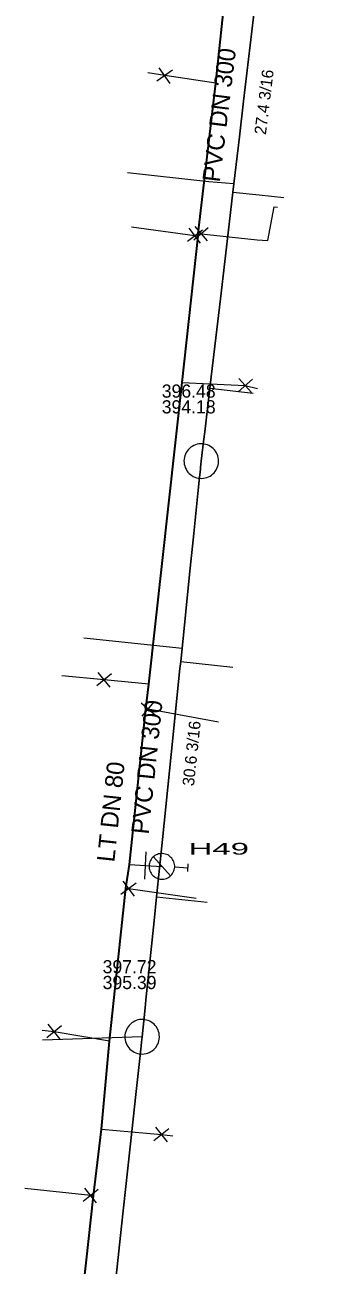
# Model space of a CAD drawing. Extents: x -772952 to -772403, y -1033777 to -1033210.
# Drawn here: x -772699.6 to -772678.8, y -1033502.9 to -1033418.1 of the extents above; entities that cross this region are included whole.
import ezdxf

# ---------------------------------------------------------------- set-up
doc = ezdxf.new("R2010")
doc.units = 0
doc.header["$LTSCALE"] = 0.36
for name, color, linetype, lineweight in [('15', 7, 'Continuous', 13), ('16', 7, 'Continuous', 35), ('2', 7, 'Continuous', 25), ('20', 7, 'Continuous', 13), ('4', 7, 'Continuous', 13), ('57', 7, 'Continuous', 13), ('59', 7, 'Continuous', 13)]:
    doc.layers.add(name, color=color, linetype=linetype, lineweight=lineweight)
for name, color, linetype in [('17', 7, 'Continuous'), ('3', 7, 'Continuous'), ('6', 7, 'Continuous')]:
    doc.layers.add(name, color=color, linetype=linetype)

msp = doc.modelspace()

# ---------------------------------------------------------------- linework, layer by layer
at = {"layer": '15'}
for p, q in [((-772689.536, -1033421.25), (-772690.602, -1033421.997)), ((-772689.699, -1033422.15), (-772690.437, -1033421.092)), ((-772687.485, -1033432.168), (-772688.52, -1033432.957)), ((-772687.612, -1033433.074), (-772688.392, -1033432.046)), ((-772688.085, -1033432.839), (-772687.098, -1033431.99)), ((-772688.012, -1033431.927), (-772687.172, -1033432.907)), ((-772685.043, -1033443.228), (-772684.08, -1033442.353)), ((-772684.995, -1033442.315), (-772684.129, -1033443.271)), ((-772693.708, -1033462.477), (-772694.713, -1033463.304)), ((-772693.801, -1033463.387), (-772694.618, -1033462.389)), ((-772691.681, -1033464.459), (-772690.695, -1033465.293)), ((-772691.607, -1033465.371), (-772690.768, -1033464.375)), ((-772691.43, -1033476.499), (-772691.327, -1033474.639)), ((-772693.063, -1033477.54), (-772692.022, -1033476.759)), ((-772692.929, -1033476.635), (-772692.157, -1033477.669)), ((-772697.113, -1033486.517), (-772698.126, -1033487.334)), ((-772697.215, -1033487.426), (-772698.023, -1033486.42)), ((-772690.694, -1033493.439), (-772689.89, -1033494.449)), ((-772690.8, -1033494.348), (-772689.783, -1033493.535)), ((-772694.717, -1033498.615), (-772695.527, -1033497.611)), ((-772694.617, -1033497.706), (-772695.629, -1033498.525))]:
    msp.add_line(p, q, dxfattribs=at)
at = {"layer": '16'}
msp.add_lwpolyline([(-772696.925, -1033516.445), (-772694.923, -1033498.129), (-772694.383, -1033493.587), (-772693.835, -1033487.579), (-772692.73, -1033477.131), (-772692.473, -1033475.508), (-772691.35, -1033464.888), (-772691.161, -1033463.185), (-772688.866, -1033442.589), (-772687.791, -1033432.589), (-772687.787, -1033432.396), (-772686.579, -1033422.136), (-772685.397, -1033410.938), (-772685.032, -1033407.78), (-772683.147, -1033392.504), (-772682.401, -1033385.967), (-772681.054, -1033374.035), (-772679.728, -1033361.771), (-772679.71, -1033361.563), (-772678.76, -1033352.949)], dxfattribs=at)
at = {"layer": '2'}
for points in [[(-772681.71, -1033398.243), (-772681.796, -1033398.917), (-772681.884, -1033399.66), (-772681.935, -1033400.093), (-772682.205, -1033402.39), (-772683.053, -1033409.588), (-772683.658, -1033414.727), (-772684.676, -1033423.371), (-772684.962, -1033425.8), (-772685.341, -1033429.02), (-772685.405, -1033429.57), (-772685.664, -1033431.77), (-772686.265, -1033436.869), (-772686.892, -1033442.194), (-772686.984, -1033442.98), (-772687.333, -1033445.942), (-772687.413, -1033446.622), (-772687.57, -1033447.95)], [(-772687.57, -1033447.95), (-772687.615, -1033448.391), (-772687.629, -1033448.53), (-772687.683, -1033449.057), (-772687.797, -1033450.161), (-772688.078, -1033452.901), (-772688.365, -1033455.697), (-772688.885, -1033460.749), (-772688.975, -1033461.634), (-772689.025, -1033462.113), (-772689.628, -1033467.986), (-772690.225, -1033473.799), (-772690.627, -1033477.704), (-772690.796, -1033479.349), (-772691.351, -1033484.758), (-772691.406, -1033485.29), (-772691.61, -1033487.27)], [(-772691.61, -1033487.27), (-772691.649, -1033487.634), (-772691.677, -1033487.891), (-772691.701, -1033488.118), (-772691.747, -1033488.542), (-772692.035, -1033491.203), (-772692.309, -1033493.741), (-772693.008, -1033500.216), (-772693.63, -1033505.97), (-772694.06, -1033509.95), (-772694.633, -1033515.304), (-772694.908, -1033517.801), (-772695.388, -1033522.246), (-772696.055, -1033528.415), (-772696.596, -1033533.419), (-772696.742, -1033534.772), (-772696.85, -1033535.77)]]:
    msp.add_lwpolyline(points, dxfattribs=at)
at = {"layer": '20'}
for p, q in [((-772689.675, -1033476.277), (-772690.843, -1033474.974)), ((-772688.477, -1033475.453), (-772688.506, -1033475.993)), ((-772689.374, -1033475.674), (-772688.491, -1033475.723))]:
    msp.add_line(p, q, dxfattribs=at)
msp.add_lwpolyline([(-772690.306, -1033476.504), (-772690.216, -1033476.505), (-772690.125, -1033476.496), (-772690.034, -1033476.477), (-772689.948, -1033476.45), (-772689.864, -1033476.412), (-772689.784, -1033476.367), (-772689.711, -1033476.313), (-772689.641, -1033476.252), (-772689.581, -1033476.183), (-772689.527, -1033476.11), (-772689.481, -1033476.031), (-772689.442, -1033475.947), (-772689.413, -1033475.86), (-772689.394, -1033475.771), (-772689.385, -1033475.679), (-772689.384, -1033475.587), (-772689.393, -1033475.497), (-772689.412, -1033475.408), (-772689.442, -1033475.32), (-772689.479, -1033475.236), (-772689.525, -1033475.157), (-772689.577, -1033475.082), (-772689.639, -1033475.015), (-772689.706, -1033474.953), (-772689.781, -1033474.899), (-772689.861, -1033474.852), (-772689.943, -1033474.816), (-772690.031, -1033474.787), (-772690.12, -1033474.768), (-772690.212, -1033474.757), (-772690.302, -1033474.758), (-772690.393, -1033474.767), (-772690.484, -1033474.786), (-772690.57, -1033474.813), (-772690.654, -1033474.851), (-772690.734, -1033474.896), (-772690.807, -1033474.95), (-772690.877, -1033475.011), (-772690.937, -1033475.079), (-772690.991, -1033475.153), (-772691.037, -1033475.232), (-772691.076, -1033475.316), (-772691.103, -1033475.403), (-772691.124, -1033475.492), (-772691.133, -1033475.583), (-772691.134, -1033475.676), (-772691.123, -1033475.766), (-772691.106, -1033475.855), (-772691.076, -1033475.943), (-772691.039, -1033476.027), (-772690.993, -1033476.106), (-772690.941, -1033476.181), (-772690.879, -1033476.248), (-772690.812, -1033476.31), (-772690.737, -1033476.364), (-772690.657, -1033476.411), (-772690.575, -1033476.447), (-772690.487, -1033476.476), (-772690.398, -1033476.495), (-772690.308, -1033476.504)], dxfattribs=at)
at = {"layer": '4'}
for points in [[(-772686.389, -1033447.95), (-772686.396, -1033447.831), (-772686.414, -1033447.714), (-772686.443, -1033447.598), (-772686.483, -1033447.487), (-772686.536, -1033447.38), (-772686.598, -1033447.279), (-772686.671, -1033447.184), (-772686.752, -1033447.098), (-772686.843, -1033447.02), (-772686.941, -1033446.951), (-772687.044, -1033446.893), (-772687.152, -1033446.846), (-772687.267, -1033446.809), (-772687.382, -1033446.784), (-772687.5, -1033446.772), (-772687.62, -1033446.771), (-772687.739, -1033446.782), (-772687.855, -1033446.805), (-772687.968, -1033446.839), (-772688.078, -1033446.885), (-772688.183, -1033446.942), (-772688.282, -1033447.009), (-772688.372, -1033447.085), (-772688.456, -1033447.17), (-772688.529, -1033447.264), (-772688.593, -1033447.364), (-772688.647, -1033447.47), (-772688.691, -1033447.581), (-772688.723, -1033447.695), (-772688.742, -1033447.813), (-772688.75, -1033447.932), (-772688.745, -1033448.05), (-772688.73, -1033448.168), (-772688.701, -1033448.284), (-772688.663, -1033448.396), (-772688.612, -1033448.504), (-772688.551, -1033448.606), (-772688.48, -1033448.702), (-772688.399, -1033448.789), (-772688.311, -1033448.869), (-772688.215, -1033448.939), (-772688.112, -1033448.999), (-772688.004, -1033449.048), (-772687.891, -1033449.086), (-772687.774, -1033449.112), (-772687.657, -1033449.127), (-772687.538, -1033449.13), (-772687.419, -1033449.121), (-772687.301, -1033449.1), (-772687.188, -1033449.067), (-772687.078, -1033449.023), (-772686.972, -1033448.968), (-772686.872, -1033448.902), (-772686.779, -1033448.827), (-772686.696, -1033448.743), (-772686.62, -1033448.651), (-772686.554, -1033448.552), (-772686.499, -1033448.447), (-772686.455, -1033448.337), (-772686.421, -1033448.223), (-772686.399, -1033448.106), (-772686.389, -1033447.987)], [(-772690.429, -1033487.27), (-772690.436, -1033487.151), (-772690.454, -1033487.034), (-772690.483, -1033486.918), (-772690.524, -1033486.807), (-772690.576, -1033486.7), (-772690.639, -1033486.599), (-772690.712, -1033486.504), (-772690.793, -1033486.418), (-772690.883, -1033486.34), (-772690.981, -1033486.271), (-772691.084, -1033486.213), (-772691.193, -1033486.166), (-772691.307, -1033486.129), (-772691.423, -1033486.104), (-772691.541, -1033486.092), (-772691.66, -1033486.091), (-772691.779, -1033486.102), (-772691.895, -1033486.125), (-772692.009, -1033486.159), (-772692.119, -1033486.205), (-772692.223, -1033486.262), (-772692.322, -1033486.329), (-772692.413, -1033486.405), (-772692.496, -1033486.49), (-772692.57, -1033486.584), (-772692.634, -1033486.684), (-772692.688, -1033486.79), (-772692.731, -1033486.901), (-772692.763, -1033487.015), (-772692.782, -1033487.133), (-772692.79, -1033487.252), (-772692.786, -1033487.37), (-772692.77, -1033487.488), (-772692.742, -1033487.604), (-772692.703, -1033487.716), (-772692.652, -1033487.824), (-772692.591, -1033487.926), (-772692.52, -1033488.022), (-772692.44, -1033488.109), (-772692.351, -1033488.189), (-772692.255, -1033488.259), (-772692.152, -1033488.319), (-772692.044, -1033488.368), (-772691.931, -1033488.406), (-772691.815, -1033488.432), (-772691.697, -1033488.447), (-772691.578, -1033488.45), (-772691.46, -1033488.441), (-772691.342, -1033488.42), (-772691.228, -1033488.387), (-772691.118, -1033488.343), (-772691.012, -1033488.288), (-772690.913, -1033488.222), (-772690.82, -1033488.147), (-772690.736, -1033488.063), (-772690.661, -1033487.971), (-772690.595, -1033487.872), (-772690.539, -1033487.767), (-772690.495, -1033487.657), (-772690.461, -1033487.543), (-772690.44, -1033487.426), (-772690.429, -1033487.307)]]:
    msp.add_lwpolyline(points, close=True, dxfattribs=at)
at = {"layer": '57'}
for p, q in [((-772686.984, -1033442.98), (-772684.02, -1033443.3)), ((-772688.885, -1033460.749), (-772695.59, -1033460.04)), ((-772688.975, -1033461.634), (-772685.41, -1033462.02)), ((-772690.627, -1033477.704), (-772687.16, -1033478.08)), ((-772691.61, -1033487.27), (-772698.407, -1033487.493))]:
    msp.add_line(p, q, dxfattribs=at)
for points in [[(-772685.341, -1033429.02), (-772687.057, -1033428.871), (-772692.62, -1033428.27)], [(-772685.405, -1033429.57), (-772683.605, -1033429.77), (-772681.93, -1033429.95)]]:
    msp.add_lwpolyline(points, dxfattribs=at)
at = {"layer": '59'}
for points in [[(-772686.58, -1033422.137), (-772690.068, -1033421.623), (-772691.227, -1033421.42)], [(-772687.788, -1033432.396), (-772683.757, -1033432.829), (-772683.027, -1033432.883), (-772682.579, -1033430.579), (-772682.372, -1033430.606)], [(-772687.792, -1033432.589), (-772688.002, -1033432.562), (-772692.334, -1033431.982)], [(-772688.866, -1033442.589), (-772684.563, -1033442.791), (-772683.725, -1033442.984)], [(-772691.161, -1033463.185), (-772694.21, -1033462.89), (-772697.09, -1033462.61)], [(-772691.351, -1033464.889), (-772691.189, -1033464.875), (-772686.401, -1033465.753)], [(-772692.474, -1033475.509), (-772691.379, -1033475.57), (-772690.259, -1033475.632)], [(-772692.731, -1033477.132), (-772692.544, -1033477.151), (-772687.918, -1033477.808)], [(-772693.836, -1033487.58), (-772697.619, -1033486.925), (-772698.445, -1033486.837)], [(-772694.384, -1033493.587), (-772690.293, -1033493.943), (-772689.504, -1033494.03)], [(-772694.923, -1033498.129), (-772695.122, -1033498.115), (-772699.626, -1033497.643)]]:
    msp.add_lwpolyline(points, dxfattribs=at)

# ---------------------------------------------------------------- texts
at = {"layer": '17'}
msp.add_text('LT DN 80', height=1.2, rotation=84, dxfattribs=at).set_placement((-772693.511, -1033475.379))
at = {"layer": '20', "width": 2.1}
msp.add_text('H49 ', height=0.8, dxfattribs=at).set_placement((-772688.432, -1033474.827))
at = {"layer": '3'}
for s, height, rotation, p in [('PVC DN 300', 1.2, 83, (-772686.308, -1033428.94)), ('27.4 3/16', 0.8, 83, (-772683.156, -1033425.687)), ('PVC DN 300', 1.2, 84, (-772691.168, -1033473.479)), ('30.6 3/16', 0.8, 84, (-772688.069, -1033470.177))]:
    msp.add_text(s, height=height, rotation=rotation, dxfattribs=at).set_placement(p)
at = {"layer": '6'}
for s, p in [('396.48', (-772690.268, -1033443.617)), ('394.18', (-772690.268, -1033444.694)), ('397.72', (-772694.308, -1033482.937)), ('395.39', (-772694.308, -1033484.014))]:
    msp.add_text(s, height=0.9, dxfattribs=at).set_placement(p)

doc.saveas('drawing.dxf')
